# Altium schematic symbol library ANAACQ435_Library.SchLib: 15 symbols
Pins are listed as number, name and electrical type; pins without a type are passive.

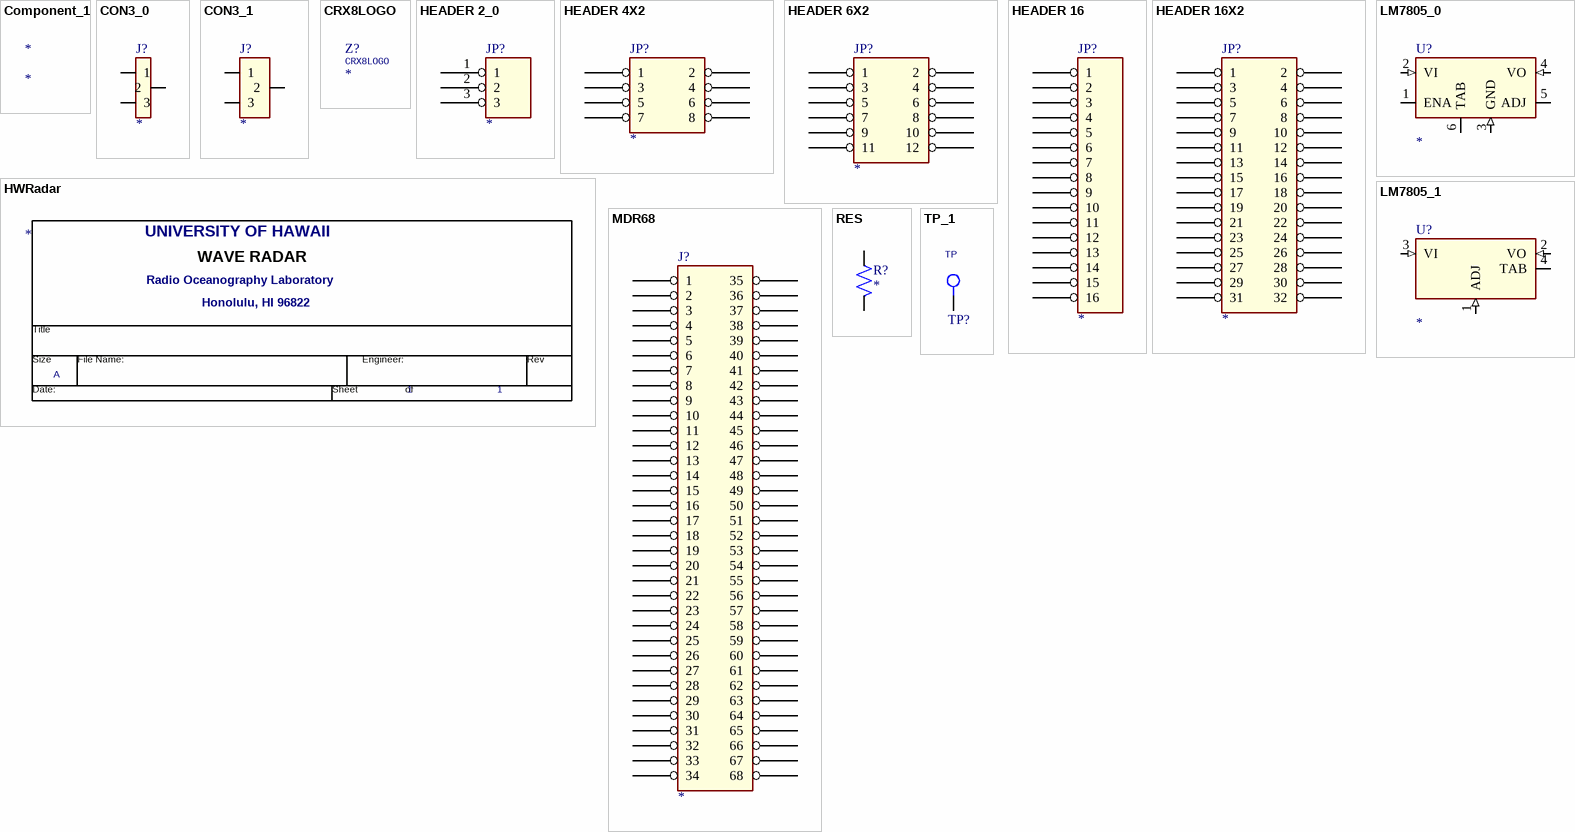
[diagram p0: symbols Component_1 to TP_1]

## Component_1
designator *

## CON3_0
designator J?
pins: 1, 2, 3

## CON3_1
designator J?
pins: 1, 2, 3

## CRX8LOGO
designator Z?
footprint CRX8TINY

## HEADER 2_0
designator JP?
pins: 1, 2, 3

## HEADER 4X2
designator JP?
pins: 1, 2, 3, 4, 5, 6, 7, 8

## HEADER 6X2
designator JP?
pins: 1, 2, 3, 4, 5, 6, 7, 8, 9, 10, 11, 12

## HEADER 16
designator JP?
pins: 1, 2, 3, 4, 5, 6, 7, 8, 9, 10, 11, 12, 13, 14, 15, 16

## HEADER 16X2
designator JP?
pins: 1, 2, 3, 4, 5, 6, 7, 8, 9, 10, 11, 12, 13, 14, 15, 16, 17, 18, 19, 20, 21, 22, 23, 24, 25, 26, 27, 28, 29, 30, 31, 32

## HWRadar
designator *  Page Count: 1  Page Size: A  OrgAddr3: Honolulu, HI 96822  OrgAddr1: Radio Oceanography Laboratory  OrgName: UNIVERSITY OF HAWAII  (graphical)
OrgAddr2: 2525 Correa Road; Engineer:: <ENG>

## LM7805_0
designator U?
footprint LM78XX-TO220
pins: 1 ENA, 2 VI (in), 3 GND (in), 4 VO (in), 5 ADJ, 6 TAB

## LM7805_1
designator U?
pins: 1 ADJ (in), 2 VO (in), 3 VI (in), 4 TAB

## MDR68
designator J?
footprint MDR68
pins: 1, 2, 3, 4, 5, 6, 7, 8, 9, 10, 11, 12, 13, 14, 15, 16, 17, 18, 19, 20, 21, 22, 23, 24, 25, 26, 27, 28, 29, 30, 31, 32, 33, 34, 35, 36, 37, 38, 39, 40, 41, 42, 43, 44, 45, 46, 47, 48, 49, 50, 51, 52, 53, 54, 55, 56, 57, 58, 59, 60, 61, 62, 63, 64, 65, 66, 67, 68

## RES
designator R?
footprint RS400
pins: 1, 2

## TP_1
designator TP?, comment TP
footprint TP
pins: 1 TP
